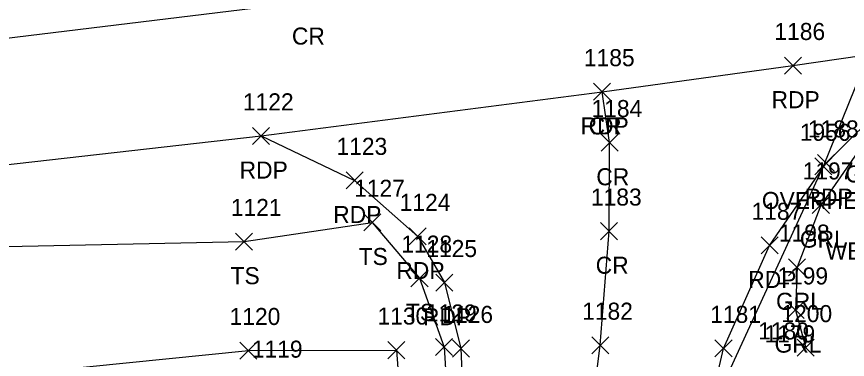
# Model space of a CAD drawing. Extents: x 1600395 to 1603269, y 874955 to 877143.
# Drawn here: x 1601626.7 to 1601724, y 875180 to 875220.3 of the extents above; entities that cross this region are included whole.
import ezdxf

# ---------------------------------------------------------------- set-up
doc = ezdxf.new("R2010")
doc.units = 0
for name, color, linetype in [('L_A', 7, 'Continuous'), ('L_I', 7, 'Continuous'), ('L_TIC', 7, 'Continuous'), ('LELB', 7, 'Continuous'), ('P_A', 7, 'Continuous'), ('P_I', 7, 'Continuous'), ('P_TIC', 7, 'Continuous'), ('PET', 7, 'Continuous'), ('PRC', 7, 'Continuous'), ('R_A', 7, 'Continuous'), ('R_I', 7, 'Continuous'), ('R_TIC', 7, 'Continuous'), ('RGR', 7, 'Continuous'), ('S_C', 7, 'Continuous'), ('S_I', 7, 'Continuous'), ('U_A', 7, 'Continuous'), ('U_I', 7, 'Continuous'), ('U_TIC', 7, 'Continuous'), ('UCO', 7, 'Continuous')]:
    doc.layers.add(name, color=color, linetype=linetype)

msp = doc.modelspace()

# ---------------------------------------------------------------- linework, layer by layer
at = {"layer": 'L_TIC'}
for points in [[(1601667.347, 875195.112), (1601669.347, 875197.112)], [(1601669.347, 875195.112), (1601667.347, 875197.112)], [(1601652.332, 875192.863), (1601654.332, 875194.863)], [(1601654.332, 875192.863), (1601652.332, 875194.863)], [(1601672.884, 875188.564), (1601674.884, 875190.564)], [(1601674.884, 875188.564), (1601672.884, 875190.564)], [(1601675.765, 875180.488), (1601677.765, 875182.488)], [(1601677.765, 875180.488), (1601675.765, 875182.488)], [(1601652.84, 875180.076), (1601654.84, 875182.076)], [(1601654.84, 875180.076), (1601652.84, 875182.076)], [(1601670.172, 875180.126), (1601672.172, 875182.126)], [(1601672.172, 875180.126), (1601670.172, 875182.126)]]:
    msp.add_lwpolyline(points, dxfattribs=at)
at = {"layer": 'LELB'}
for points in [[(1601505.584, 875186.841), (1601543.498, 875188.163), (1601578.086, 875189.845), (1601619.87, 875193.155), (1601653.332, 875193.863), (1601668.347, 875196.112), (1601673.884, 875189.564), (1601676.765, 875181.488), (1601678.04, 875161.078), (1601676.089, 875147.885), (1601668.379, 875110.491), (1601657.668, 875076.04)], [(1601505.235, 875162.403), (1601544.115, 875168.6), (1601558.578, 875179.791), (1601582.314, 875176.109), (1601620.874, 875177.75), (1601653.84, 875181.076), (1601671.172, 875181.126), (1601672.7, 875160.584), (1601672.894, 875148.092), (1601664.484, 875114.32), (1601659.555, 875083.818), (1601652.568, 875078.374)]]:
    msp.add_lwpolyline(points, dxfattribs=at)
at = {"layer": 'P_TIC'}
for points in [[(1601716.657, 875213.505), (1601718.657, 875215.505)], [(1601718.657, 875213.505), (1601716.657, 875215.505)], [(1601694.275, 875210.435), (1601696.275, 875212.435)], [(1601696.275, 875210.435), (1601694.275, 875212.435)], [(1601694.275, 875210.435), (1601696.275, 875212.435)], [(1601696.275, 875210.435), (1601694.275, 875212.435)], [(1601654.314, 875205.252), (1601656.314, 875207.252)], [(1601656.314, 875205.252), (1601654.314, 875207.252)], [(1601654.314, 875205.252), (1601656.314, 875207.252)], [(1601656.314, 875205.252), (1601654.314, 875207.252)], [(1601695.172, 875204.464), (1601697.172, 875206.464)], [(1601697.172, 875204.464), (1601695.172, 875206.464)], [(1601720.533, 875202.075), (1601722.533, 875204.075)], [(1601722.533, 875202.075), (1601720.533, 875204.075)], [(1601665.285, 875200.032), (1601667.285, 875202.032)], [(1601667.285, 875200.032), (1601665.285, 875202.032)], [(1601672.685, 875193.463), (1601674.685, 875195.463)], [(1601674.685, 875193.463), (1601672.685, 875195.463)], [(1601695.102, 875194.085), (1601697.102, 875196.085)], [(1601697.102, 875194.085), (1601695.102, 875196.085)], [(1601713.923, 875192.415), (1601715.923, 875194.415)], [(1601715.923, 875192.415), (1601713.923, 875194.415)], [(1601675.806, 875188.048), (1601677.806, 875190.048)], [(1601677.806, 875188.048), (1601675.806, 875190.048)], [(1601694.071, 875180.696), (1601696.071, 875182.696)], [(1601696.071, 875180.696), (1601694.071, 875182.696)], [(1601677.738, 875180.317), (1601679.738, 875182.317)], [(1601679.738, 875180.317), (1601677.738, 875182.317)], [(1601708.513, 875180.324), (1601710.513, 875182.324)], [(1601710.513, 875180.324), (1601708.513, 875182.324)]]:
    msp.add_lwpolyline(points, dxfattribs=at)
at = {"layer": 'PET'}
for points in [[(1601408.553, 875202.716), (1601438.204, 875198.664), (1601469.017, 875195.647), (1601497.71, 875194.55), (1601505.99, 875194.415), (1601542.595, 875195.343), (1601577.581, 875198.029), (1601619.125, 875202.154), (1601655.314, 875206.252), (1601695.275, 875211.435), (1601717.657, 875214.505), (1601739.733, 875217.719), (1601747.535, 875218.619)], [(1601673.093, 875021.696), (1601681.133, 875058.084), (1601690.373, 875095.308), (1601698.183, 875129.886), (1601704.679, 875160.327), (1601709.513, 875181.324), (1601714.923, 875193.415), (1601721.533, 875203.075), (1601729.108, 875210.606), (1601733.529, 875213.857), (1601739.733, 875217.719)], [(1601655.314, 875206.252), (1601666.285, 875201.032), (1601673.685, 875194.463), (1601676.806, 875189.048), (1601678.738, 875181.317), (1601679.602, 875161.131), (1601678.619, 875146.746), (1601670.887, 875109.659), (1601661.849, 875070.373), (1601658.601, 875056.472), (1601651.571, 875026.414)]]:
    msp.add_lwpolyline(points, dxfattribs=at)
at = {"layer": 'PRC'}
for points in [[(1601506.675, 875209.64), (1601547.643, 875210.928), (1601581.16, 875213.374), (1601623.527, 875217.485), (1601660.498, 875221.967), (1601694.047, 875226.221), (1601722.769, 875230.164), (1601754.149, 875234.472)], [(1601662.483, 875023.749), (1601671.39, 875061.762), (1601679.377, 875096.605), (1601687.383, 875132.88), (1601692.14, 875158.223), (1601695.071, 875181.696), (1601696.102, 875195.085), (1601696.172, 875205.464), (1601695.275, 875211.435)]]:
    msp.add_lwpolyline(points, dxfattribs=at)
at = {"layer": 'R_TIC'}
for points in [[(1601719.919, 875197.149), (1601721.919, 875199.149)], [(1601721.919, 875197.149), (1601719.919, 875199.149)], [(1601717.127, 875189.856), (1601719.127, 875191.856)], [(1601719.127, 875189.856), (1601717.127, 875191.856)], [(1601716.952, 875184.834), (1601718.952, 875186.834)], [(1601718.952, 875184.834), (1601716.952, 875186.834)], [(1601718.154, 875180.414), (1601720.154, 875182.414)], [(1601720.154, 875180.414), (1601718.154, 875182.414)]]:
    msp.add_lwpolyline(points, dxfattribs=at)
at = {"layer": 'RGR'}
msp.add_lwpolyline([(1601746.172, 875217.107), (1601739.05, 875215.092), (1601732.525, 875211.8), (1601726.237, 875205.794), (1601720.919, 875198.149), (1601718.127, 875190.856), (1601717.952, 875185.834), (1601719.154, 875181.414)], dxfattribs=at)
at = {"layer": 'U_TIC'}
for points in [[(1601720.199, 875201.682), (1601722.199, 875203.682)], [(1601722.199, 875201.682), (1601720.199, 875203.682)]]:
    msp.add_lwpolyline(points, dxfattribs=at)
at = {"layer": 'UCO'}
msp.add_lwpolyline([(1601739.016, 875246.802), (1601721.199, 875202.682), (1601687.29, 875128.811)], dxfattribs=at)

# ---------------------------------------------------------------- texts
at = {"layer": 'L_A'}
for p in [(1601666.757, 875191.112), (1601651.742, 875188.863), (1601672.293, 875184.564)]:
    msp.add_text('TS', height=2, dxfattribs=at).set_placement(p)
at = {"layer": 'L_I'}
for s, p in [('1127', (1601666.222, 875199.112)), ('1121', (1601651.773, 875196.863)), ('1128', (1601671.758, 875192.564)), ('1129', (1601674.632, 875184.488)), ('1120', (1601651.627, 875184.076)), ('1130', (1601668.96, 875184.126)), ('1119', (1601654.234, 875180.242))]:
    msp.add_text(s, height=2, dxfattribs=at).set_placement(p)
at = {"layer": 'P_A'}
for s, p in [('CR', (1601658.931, 875216.967)), ('RDP', (1601715.145, 875209.505)), ('RDP', (1601692.763, 875206.435)), ('CR', (1601693.708, 875206.435)), ('RDP', (1601652.802, 875201.252)), ('RDP', (1601652.802, 875201.252)), ('CR', (1601694.605, 875200.464)), ('RDP', (1601719.021, 875198.075)), ('RDP', (1601663.773, 875196.032)), ('RDP', (1601671.173, 875189.463)), ('CR', (1601694.535, 875190.085)), ('RDP', (1601712.411, 875188.415)), ('RDP', (1601674.294, 875184.048))]:
    msp.add_text(s, height=2, dxfattribs=at).set_placement(p)
at = {"layer": 'P_I'}
for s, p in [('1186', (1601715.477, 875217.505)), ('1185', (1601693.15, 875214.435)), ('1185', (1601693.15, 875214.435)), ('1122', (1601653.188, 875209.252)), ('1122', (1601653.188, 875209.252)), ('1184', (1601694.046, 875208.464)), ('1188', (1601719.407, 875206.075)), ('1123', (1601664.159, 875204.032)), ('1183', (1601693.976, 875198.085)), ('1124', (1601671.559, 875197.463)), ('1187', (1601712.797, 875196.415)), ('1125', (1601674.68, 875192.048)), ('1182', (1601692.945, 875184.696)), ('1126', (1601676.557, 875184.317)), ('1181', (1601707.954, 875184.324))]:
    msp.add_text(s, height=2, dxfattribs=at).set_placement(p)
at = {"layer": 'R_A'}
for p in [(1601723.781, 875200.794), (1601718.463, 875193.149), (1601715.67, 875185.856), (1601715.495, 875180.834)]:
    msp.add_text('GRL', height=2, dxfattribs=at).set_placement(p)
at = {"layer": 'R_I'}
for s, p in [('1197', (1601718.794, 875201.149)), ('1198', (1601716.001, 875193.856)), ('1199', (1601715.819, 875188.834)), ('1200', (1601716.296, 875184.414))]:
    msp.add_text(s, height=2, dxfattribs=at).set_placement(p)
at = {"layer": 'S_C'}
msp.add_text('WEST HILL RD', height=2, dxfattribs=at).set_placement((1601721.485, 875191.753))
at = {"layer": 'S_I'}
for s, p in [('1180', (1601713.57, 875182.381)), ('1179', (1601714.31, 875182.039))]:
    msp.add_text(s, height=2, dxfattribs=at).set_placement(p)
at = {"layer": 'U_A'}
msp.add_text('OVERHEAD', height=2, dxfattribs=at).set_placement((1601714.01, 875197.682))
at = {"layer": 'U_I'}
msp.add_text('1956', height=2, dxfattribs=at).set_placement((1601718.451, 875205.682))

doc.saveas('drawing.dxf')
